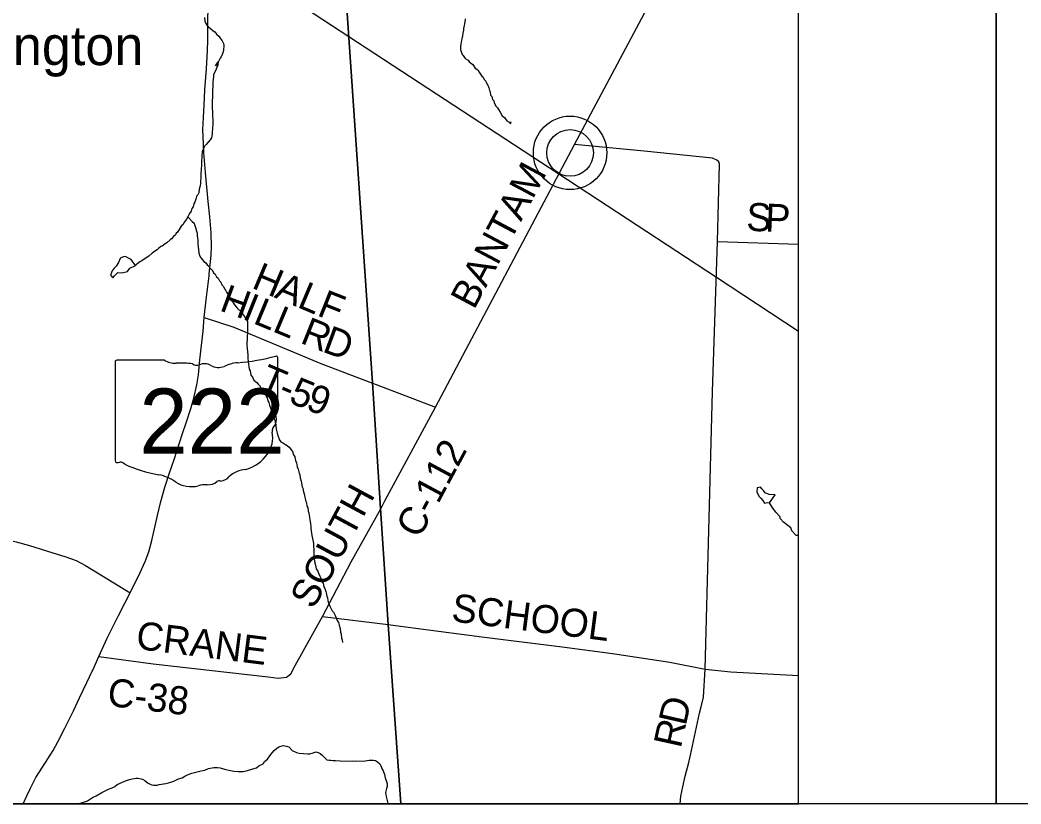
# Model space of a CAD drawing. Extents: x 0 to 39.3, y -3.9 to 22.
# Drawn here: x 7.123 to 9.15, y 13.9 to 15.488 of the extents above; entities that cross this region are included whole.
import ezdxf

# ---------------------------------------------------------------- set-up
doc = ezdxf.new("R2010")
doc.units = 0
for name, color, linetype in [('GM_X_Corporation', 7, 'Continuous'), ('GM_X_County_Road', 7, 'Continuous'), ('GM_X_County_Road_Text', 7, 'Continuous'), ('GM_X_Minor_Lake', 7, 'Continuous'), ('GM_X_Minor_River', 7, 'Continuous'), ('GM_X_Rail_Line', 7, 'Continuous'), ('GM_X_State_Location', 7, 'Continuous'), ('GM_X_State_Route', 7, 'Continuous'), ('GM_X_State_Shield', 7, 'Continuous'), ('GM_X_Township_Road', 7, 'Continuous'), ('GM_X_Township_Road_Text', 7, 'Continuous'), ('GM_X_Unincorporated', 7, 'Continuous'), ('GM_X_Unincorporated_Location', 7, 'Continuous'), ('GM_X_Unincorporated_Text', 7, 'Continuous'), ('SH_Data', 7, 'Continuous'), ('SH_Text', 7, 'Continuous')]:
    doc.layers.add(name, color=color, linetype=linetype)

msp = doc.modelspace()

# ---------------------------------------------------------------- linework, layer by layer
at = {"layer": 'GM_X_Corporation'}
msp.add_lwpolyline([(7.894, 13.9), (8.7, 13.9), (8.7, 17.1372), (7.6633, 17.2343), (7.7024, 16.7078), (7.7245, 16.3862), (7.7384, 16.1852), (7.7467, 16.0631), (7.8368, 14.7531), (7.8533, 14.4986), (7.8685, 14.2638)], close=True, dxfattribs=at)
msp.add_lwpolyline([(3.8692, 13.9), (7.894, 13.9), (7.8685, 14.2638), (7.8533, 14.4986), (7.8368, 14.7531), (7.7467, 16.0631)], dxfattribs=at)
at = {"layer": 'GM_X_County_Road'}
for points in [[(7.8619, 14.5137), (7.9642, 14.7038), (8.2458, 15.2359), (8.4264, 15.5749), (8.4473, 15.6168), (8.4536, 15.6361), (8.4563, 15.6574), (8.4613, 15.7093), (8.4729, 15.8197), (8.4859, 15.9546)], [(6.0819, 14.5477), (6.1075, 14.544), (6.1751, 14.5372), (6.2211, 14.532), (6.2642, 14.5267), (6.488, 14.5027), (6.5996, 14.4912), (6.8005, 14.4678), (7.0043, 14.4459), (7.0661, 14.4409), (7.0915, 14.4369), (7.1149, 14.4309), (7.1423, 14.4234), (7.1872, 14.4095), (7.2156, 14.4005), (7.2365, 14.393), (7.2555, 14.3831), (7.2799, 14.3681), (7.3458, 14.3278)], [(7.7356, 14.2798), (7.7938, 14.3902), (7.8535, 14.4981), (7.8619, 14.5137)], [(7.2825, 14.1984), (7.3922, 14.184), (7.6254, 14.1576), (7.6458, 14.155), (7.6627, 14.1568), (7.6715, 14.1634), (7.6802, 14.1808), (7.7356, 14.2798), (7.8688, 14.2633), (7.8933, 14.2601)], [(7.8933, 14.2601), (8.0581, 14.2387), (8.2213, 14.2186), (8.3233, 14.2046), (8.439, 14.1869), (8.5108, 14.1731)], [(8.5108, 14.1731), (8.5626, 14.1676), (8.7, 14.1603)]]:
    msp.add_lwpolyline(points, dxfattribs=at)
at = {"layer": 'GM_X_Minor_Lake'}
for points in [[(7.3322, 15.0079), (7.3268, 15.0064), (7.3257, 15.0049), (7.3221, 14.997), (7.3174, 14.9895), (7.3136, 14.985), (7.3093, 14.9798), (7.3061, 14.9707), (7.3109, 14.9653), (7.3141, 14.9698), (7.321, 14.9761), (7.329, 14.976), (7.3404, 14.9785), (7.3451, 14.9852), (7.3567, 14.9908)], [(7.3567, 14.9908), (7.3478, 15.0026), (7.3413, 15.0062), (7.3367, 15.0089), (7.3322, 15.0079)], [(8.6413, 14.5102), (8.6525, 14.5258), (8.6404, 14.5271), (8.6325, 14.5299), (8.6287, 14.5346), (8.6258, 14.5384), (8.6228, 14.5415), (8.6163, 14.5405), (8.615, 14.5321), (8.6191, 14.5237), (8.6232, 14.5191), (8.6273, 14.5144)], [(8.6273, 14.5144), (8.6306, 14.5091), (8.636, 14.5106), (8.6413, 14.5102)]]:
    msp.add_lwpolyline(points, dxfattribs=at)
at = {"layer": 'GM_X_Minor_River'}
for points in [[(7.4968, 15.4926), (7.4974, 15.4853), (7.4993, 15.4807), (7.5015, 15.4773), (7.5048, 15.4738), (7.5142, 15.4656), (7.5172, 15.4637), (7.5206, 15.459), (7.5254, 15.4548), (7.528, 15.4509), (7.5325, 15.4455), (7.5351, 15.4401), (7.5354, 15.4367), (7.5352, 15.4261), (7.5336, 15.4211), (7.53, 15.4132), (7.5281, 15.4102), (7.5257, 15.4053), (7.5225, 15.4), (7.5186, 15.3947), (7.5241, 15.403)], [(8.0248, 15.4903), (8.0244, 15.4872), (8.0231, 15.4804), (8.0223, 15.4766), (8.0214, 15.4705), (8.021, 15.4671), (8.0197, 15.461), (8.0189, 15.4557), (8.0176, 15.4496), (8.0168, 15.447), (8.0159, 15.439), (8.0151, 15.4341), (8.0149, 15.4272), (8.0164, 15.4238), (8.0182, 15.418), (8.0208, 15.4157), (8.0245, 15.4096), (8.0305, 15.4064), (8.0324, 15.4033), (8.0403, 15.3979), (8.0451, 15.3902), (8.05, 15.387), (8.0526, 15.3821), (8.0585, 15.3743), (8.0611, 15.372), (8.063, 15.3674), (8.0663, 15.3639), (8.0685, 15.3582), (8.0707, 15.3555), (8.0722, 15.3505), (8.074, 15.3448), (8.0751, 15.3421), (8.0761, 15.3356), (8.0783, 15.3329), (8.0801, 15.3268), (8.0823, 15.3241), (8.0834, 15.321), (8.0867, 15.3133), (8.0901, 15.3102), (8.0923, 15.3064), (8.0953, 15.3014), (8.0993, 15.2937), (8.1042, 15.2902), (8.1086, 15.2836), (8.1135, 15.2809), (8.1165, 15.2778), (8.1178, 15.2823)], [(7.5241, 15.403), (7.5232, 15.3962), (7.5181, 15.3833), (7.5145, 15.3773), (7.5145, 15.3743), (7.5139, 15.3663), (7.5135, 15.3632), (7.513, 15.3355), (7.5125, 15.3313), (7.512, 15.3244), (7.5119, 15.3145), (7.5121, 15.3077), (7.5124, 15.3035), (7.5127, 15.2955), (7.513, 15.2928), (7.5133, 15.2864), (7.5131, 15.2749), (7.5126, 15.2711), (7.5125, 15.267), (7.512, 15.2613), (7.512, 15.2582), (7.5115, 15.2529), (7.5107, 15.2491), (7.5079, 15.245), (7.5041, 15.2405), (7.5002, 15.2356), (7.4975, 15.2333), (7.4943, 15.2277), (7.4915, 15.2205), (7.491, 15.2129), (7.4907, 15.1992), (7.4902, 15.1912), (7.4898, 15.1886), (7.4897, 15.1828), (7.4892, 15.1783), (7.4891, 15.1692), (7.4885, 15.16), (7.4885, 15.1574), (7.488, 15.152), (7.486, 15.1452), (7.4851, 15.138), (7.4831, 15.1339), (7.4804, 15.1309), (7.4795, 15.1267), (7.4767, 15.1191), (7.4751, 15.1157), (7.4735, 15.1093), (7.4708, 15.1059), (7.4692, 15.1006), (7.4664, 15.0957), (7.4625, 15.0889), (7.4593, 15.0833), (7.4551, 15.0784), (7.4531, 15.0735), (7.4492, 15.0701), (7.4472, 15.0667), (7.4421, 15.0581), (7.4394, 15.0558), (7.4375, 15.0528), (7.4336, 15.0494), (7.4297, 15.0446), (7.427, 15.0423), (7.42, 15.0364), (7.4166, 15.0345), (7.4108, 15.03), (7.4081, 15.0289), (7.4035, 15.0248), (7.4004, 15.0222), (7.393, 15.0174), (7.3904, 15.0159), (7.3834, 15.0092), (7.3784, 15.0062), (7.3695, 15.0003), (7.3657, 14.9981), (7.3595, 14.9936), (7.3567, 14.9908)], [(7.4625, 15.0889), (7.4716, 15.0797), (7.4753, 15.0766), (7.476, 15.0739), (7.4789, 15.0655), (7.4796, 15.0621), (7.4814, 15.056), (7.4817, 15.0506), (7.482, 15.0472), (7.4827, 15.0419), (7.4833, 15.035), (7.484, 15.0274), (7.4843, 15.0228), (7.4853, 15.0156), (7.4867, 15.0117), (7.4878, 15.0083), (7.49, 15.0056), (7.4949, 14.999), (7.4986, 14.9967), (7.5016, 14.9921), (7.505, 14.9893), (7.5079, 14.9843), (7.5117, 14.9816), (7.5146, 14.9758), (7.5184, 14.9731), (7.5209, 14.9677), (7.5243, 14.965), (7.5269, 14.9596), (7.5295, 14.9569), (7.5317, 14.9512), (7.5347, 14.9481), (7.5369, 14.9435), (7.5391, 14.9408), (7.5409, 14.9366), (7.5447, 14.9319), (7.545, 14.9289), (7.5487, 14.9227), (7.5509, 14.9196), (7.555, 14.9142), (7.5572, 14.9112), (7.5613, 14.9065), (7.5636, 14.9038), (7.5699, 14.8972), (7.5733, 14.893), (7.5755, 14.8899), (7.5818, 14.8807), (7.5836, 14.8772), (7.5838, 14.8677), (7.5834, 14.8624), (7.5836, 14.8532), (7.5831, 14.8487), (7.5826, 14.8395), (7.5821, 14.8357), (7.5824, 14.8281), (7.5831, 14.8239), (7.5833, 14.8148), (7.584, 14.8106), (7.5845, 14.8014), (7.5852, 14.7972), (7.5859, 14.7896), (7.5866, 14.7866), (7.5868, 14.7809), (7.5887, 14.7774), (7.5904, 14.7686), (7.5938, 14.7644), (7.5963, 14.7582), (7.6023, 14.7536), (7.6053, 14.7501), (7.6079, 14.7474), (7.6105, 14.7431), (7.6143, 14.7408), (7.6161, 14.7366), (7.6187, 14.7335), (7.6205, 14.727), (7.6231, 14.7228), (7.6249, 14.7166), (7.6267, 14.7132), (7.6281, 14.7074), (7.6307, 14.7005), (7.6321, 14.6971), (7.6335, 14.6895), (7.6361, 14.6856), (7.6375, 14.6799), (7.639, 14.6772), (7.6397, 14.6734), (7.6408, 14.6684), (7.6411, 14.6638), (7.6421, 14.6562), (7.6439, 14.6508), (7.646, 14.6443), (7.6468, 14.6417), (7.6478, 14.6382), (7.6508, 14.6332), (7.6549, 14.6312)], [(7.6549, 14.6312), (7.664, 14.6261), (7.6681, 14.6226), (7.6726, 14.6165), (7.6748, 14.6138), (7.6766, 14.6069), (7.6796, 14.603), (7.6809, 14.5954), (7.6828, 14.5912), (7.6845, 14.5828), (7.6863, 14.5778), (7.6881, 14.5698), (7.6899, 14.5663), (7.6906, 14.5606), (7.692, 14.5537), (7.6931, 14.5499), (7.6944, 14.5426), (7.6959, 14.5396), (7.6969, 14.5323), (7.6984, 14.5281), (7.6994, 14.5216), (7.7005, 14.5189), (7.7015, 14.5128), (7.703, 14.5097), (7.704, 14.5033), (7.7055, 14.5002), (7.7065, 14.4929), (7.7076, 14.4899), (7.7082, 14.4842), (7.7089, 14.4811), (7.7096, 14.4758), (7.7103, 14.4719), (7.7114, 14.4677), (7.7116, 14.462), (7.712, 14.4582), (7.714, 14.4437), (7.7154, 14.4376), (7.7164, 14.4307), (7.7171, 14.4273), (7.7174, 14.4201), (7.7181, 14.4166), (7.718, 14.4113), (7.7182, 14.4044), (7.7184, 14.3961), (7.7195, 14.3926), (7.7202, 14.3877), (7.7216, 14.3838), (7.723, 14.3762), (7.7264, 14.3716), (7.7274, 14.3674), (7.73, 14.3612), (7.7318, 14.3585), (7.7336, 14.3513), (7.7366, 14.347), (7.738, 14.3401), (7.7402, 14.3363), (7.742, 14.3302), (7.7431, 14.3275), (7.7441, 14.3206), (7.7456, 14.3172), (7.7466, 14.3122), (7.7477, 14.3076), (7.7502, 14.3004), (7.7517, 14.2977), (7.7554, 14.2915), (7.7576, 14.2888), (7.7613, 14.2819), (7.7653, 14.2719), (7.7679, 14.2673), (7.7693, 14.262), (7.7711, 14.2555), (7.7721, 14.2478), (7.7735, 14.2436), (7.7742, 14.236), (7.7752, 14.2322), (7.7763, 14.2272)], [(8.7, 14.4437), (8.6949, 14.4438), (8.6859, 14.4531), (8.6845, 14.4592), (8.6691, 14.4709), (8.6635, 14.4774), (8.6621, 14.482), (8.6535, 14.4913), (8.6465, 14.5013), (8.6413, 14.5102)], [(7.2311, 13.9), (7.2336, 13.9003), (7.2401, 13.9013), (7.2447, 13.9016), (7.2496, 13.9031), (7.2596, 13.9067), (7.2696, 13.913), (7.2773, 13.9163), (7.2888, 13.9233), (7.2977, 13.9277), (7.3023, 13.9299), (7.3092, 13.9329), (7.3149, 13.9354), (7.3196, 13.9395), (7.3303, 13.9439), (7.3368, 13.9468), (7.3445, 13.9497), (7.3502, 13.9508), (7.3579, 13.9522), (7.3621, 13.9521), (7.3712, 13.9504), (7.3753, 13.9473), (7.3809, 13.943), (7.3862, 13.9399), (7.39, 13.9387), (7.3938, 13.9379), (7.4006, 13.9381), (7.4048, 13.9392), (7.4182, 13.9412), (7.4236, 13.9431), (7.4285, 13.9445), (7.4343, 13.9463), (7.4439, 13.9507), (7.4515, 13.9532), (7.4569, 13.9562), (7.4623, 13.9588), (7.4711, 13.9624), (7.4872, 13.9667), (7.4933, 13.9681), (7.4971, 13.9688), (7.5044, 13.9717), (7.5155, 13.9738), (7.5231, 13.9737), (7.528, 13.9732), (7.5326, 13.972), (7.5398, 13.9696), (7.5458, 13.9683), (7.5561, 13.9663), (7.5648, 13.9657), (7.5751, 13.9659), (7.5835, 13.9677), (7.5942, 13.9709), (7.6019, 13.9731), (7.6065, 13.9772), (7.615, 13.9816), (7.6181, 13.9861), (7.6239, 13.991), (7.629, 13.9974), (7.6333, 14.0034), (7.6379, 14.0086), (7.6433, 14.0131), (7.6472, 14.0157), (7.6556, 14.0182), (7.6628, 14.0173), (7.667, 14.0157), (7.6744, 14.008), (7.6831, 14.0044), (7.6881, 14.0032), (7.6972, 14.0023), (7.7059, 14.0017), (7.7097, 14.0017), (7.7147, 14.0031), (7.7185, 14.0042), (7.7227, 14.0053), (7.7269, 14.0044), (7.7311, 14.0025), (7.7348, 13.9986), (7.7393, 13.9939), (7.7445, 13.9897), (7.7487, 13.9888), (7.7525, 13.9884), (7.7567, 13.9883), (7.7616, 13.9878), (7.7715, 13.9873), (7.7963, 13.9869), (7.8016, 13.9872), (7.8183, 13.9869), (7.8222, 13.9872), (7.8298, 13.9886)], [(7.8298, 13.9886), (7.8336, 13.9889), (7.8389, 13.9888), (7.8431, 13.9883), (7.8472, 13.9852), (7.8517, 13.9813), (7.8536, 13.9771), (7.8565, 13.9706), (7.8583, 13.9668), (7.8609, 13.9599), (7.8626, 13.953), (7.8652, 13.9457), (7.8666, 13.9407), (7.8665, 13.9354), (7.8653, 13.9313), (7.8632, 13.9233), (7.8642, 13.9153), (7.8657, 13.9096), (7.8682, 13.9015), (7.8689, 13.9)], [(8.7, 13.9031), (8.6992, 13.9025), (8.6971, 13.9)]]:
    msp.add_lwpolyline(points, dxfattribs=at)
at = {"layer": 'GM_X_Rail_Line'}
msp.add_lwpolyline([(5.9697, 16.6744), (6.1991, 16.4081), (6.2218, 16.3901), (6.3667, 16.3031), (6.4893, 16.2389), (7.0583, 15.9241), (7.1182, 15.89), (7.5253, 15.6271), (8.2122, 15.1777), (8.5334, 14.9668), (8.7, 14.8573)], dxfattribs=at)
at = {"layer": 'GM_X_State_Route'}
for points in [[(7.5062, 14.9738), (7.5079, 14.9918), (7.5101, 15.0116), (7.5109, 15.0289), (7.5099, 15.057), (7.5076, 15.0895), (7.5041, 15.1204), (7.4986, 15.1789), (7.4952, 15.2192), (7.4944, 15.2368), (7.4931, 15.2662), (7.4943, 15.2903), (7.4956, 15.3156), (7.4974, 15.3466), (7.5005, 15.3886), (7.5027, 15.4261), (7.503, 15.4463), (7.5032, 15.4895), (7.5041, 15.5091), (7.506, 15.5264), (7.511, 15.5543), (7.5122, 15.5592)], [(7.27, 14.1711), (7.2825, 14.1984), (7.2992, 14.2357), (7.3224, 14.282), (7.3353, 14.3065), (7.3458, 14.3278), (7.3661, 14.3691), (7.3763, 14.391), (7.3834, 14.4105), (7.3898, 14.4337), (7.4015, 14.4845), (7.4078, 14.5126), (7.416, 14.5415), (7.4256, 14.5704), (7.4348, 14.598), (7.4521, 14.6505), (7.4596, 14.6718), (7.4694, 14.7033), (7.4752, 14.7221), (7.481, 14.7491), (7.4844, 14.7693), (7.4871, 14.7995), (7.4938, 14.8578), (7.496, 14.885), (7.5002, 14.9211), (7.5046, 14.9588), (7.5058, 14.9698), (7.5062, 14.9738)], [(7.1294, 13.9), (7.1369, 13.9165), (7.1439, 13.9323), (7.155, 13.9538), (7.1681, 13.9745), (7.1793, 13.9917), (7.1898, 14.0085), (7.1996, 14.0256), (7.2135, 14.0533), (7.2313, 14.0888), (7.2431, 14.1151), (7.258, 14.1462), (7.2692, 14.1693), (7.27, 14.1711)]]:
    msp.add_lwpolyline(points, dxfattribs=at)
at = {"layer": 'GM_X_State_Shield'}
for p, q in [((7.6451, 14.6992), (7.6451, 14.8039)), ((7.3155, 14.7955), (7.3155, 14.5954)), ((7.4153, 14.7989), (7.3187, 14.7989)), ((7.645, 14.6992), (7.6451, 14.6992))]:
    msp.add_line(p, q, dxfattribs=at)
for centre, major_axis, start_param, end_param in [((7.5277, 15.0718), (0.3495, 0), 4.814394, 5.042369), ((7.6414, 14.8043), (0.00367, 0), 6.141152, 7.989035), ((7.3193, 14.7959), (0.00382, 0), 1.712693, 3.28349), ((7.4382, 14.8222), (0.037, 0), 4.042523, 4.731795), ((7.4505, 14.6866), (0.133, 0), 1.404758, 1.657858), ((7.4807, 14.797), (0.0107, 0), 3.836095, 5.185415), ((7.4964, 14.7738), (0.0222, 0), 0.950623, 2.079405), ((7.5251, 14.8055), (0.0267, 0), 4.081561, 5.145723), ((7.5723, 14.7378), (0.0703, 0), 1.699011, 2.107814), ((7.6442, 14.6915), (0.00568, 0), 1.883978, 3.671073), ((7.6081, 14.6783), (0.0341, 0), 5.934695, 6.695948), ((7.6412, 14.6988), (0.00393, 0), 5.05454, 6.418171), ((7.6582, 14.6554), (0.0248, 0), 2.387724, 3.262537), ((7.5473, 14.6421), (0.0874, 0), 5.101752, 6.440018), ((7.3193, 14.5949), (0.00385, 0), 3.00124, 4.508301), ((7.3199, 14.6154), (0.0294, 0), 4.665946, 4.897461), ((7.3259, 14.5838), (0.0106, 0), 0.519207, 1.627899), ((7.4597, 14.7636), (0.2524, 0), 4.195997, 4.488961), ((7.3845, 14.5055), (0.079, 0), 0.823519, 1.323587), ((7.5235, 14.576), (0.0282, 0), 4.937069, 5.64225), ((7.5841, 14.5392), (0.0479, 0), 1.647645, 2.488434), ((7.4699, 14.5828), (0.0501, 0), 4.026481, 4.996735), ((7.4988, 14.5136), (0.0412, 0), 1.495662, 1.94098), ((7.5025, 14.5678), (0.0267, 0), 4.691044, 5.507374), ((7.5267, 14.5485), (0.00752, 0), 1.147584, 2.315152)]:
    msp.add_ellipse(centre, major_axis=major_axis, ratio=0.8, start_param=start_param, end_param=end_param, dxfattribs=at)
at = {"layer": 'GM_X_Township_Road'}
for p, q in [((8.5359, 15.0392), (8.7, 15.0337)), ((7.8444, 14.7497), (7.9642, 14.7038))]:
    msp.add_line(p, q, dxfattribs=at)
for points in [[(8.4603, 13.9), (8.4616, 13.9156), (8.4653, 13.9349), (8.4701, 13.9565), (8.4777, 13.9842), (8.4812, 13.9987), (8.4995, 14.0836), (8.5028, 14.097), (8.5076, 14.1161), (8.5108, 14.1731), (8.5253, 14.7348), (8.5359, 15.0392), (8.5398, 15.1959), (8.5381, 15.2006), (8.5342, 15.2042), (8.5256, 15.2078), (8.3871, 15.2223), (8.2458, 15.2359)], [(7.496, 14.885), (7.556, 14.8659), (7.732, 14.7922), (7.837, 14.7526), (7.8444, 14.7497)]]:
    msp.add_lwpolyline(points, dxfattribs=at)
at = {"layer": 'GM_X_Unincorporated'}
for radius in [0.0744, 0.0472]:
    msp.add_circle((8.237, 15.2187), radius, dxfattribs=at)
at = {"layer": 'GM_X_Unincorporated_Location'}
msp.add_line((8.237, 15.2187), (8.237, 15.2187), dxfattribs=at)
at = {"layer": 'SH_Data'}
msp.add_lwpolyline([(1.9, 21.1), (9.1, 21.1), (9.1, 13.9), (1.9, 13.9)], close=True, dxfattribs=at)
at = {"layer": 'SH_Text'}
msp.add_lwpolyline([(9.1, 21.1), (11.7047, 21.1), (11.7047, 13.9), (9.1, 13.9)], close=True, dxfattribs=at)

# ---------------------------------------------------------------- texts
at = {"layer": 'GM_X_County_Road_Text'}
for s, rotation, p in [('BANTAM', 62.012, (8.0425, 14.8994)), ('C-112', 61.7166, (7.9316, 14.4353)), ('SOUTH', 61.6855, (7.7173, 14.2924)), ('SCHOOL', 352.7468, (7.995, 14.2703)), ('CRANE', 352.8747, (7.3558, 14.2144)), ('C-38', 353.0887, (7.2978, 14.0992))]:
    msp.add_text(s, height=0.05682, rotation=rotation, dxfattribs=at).set_placement(p)
at = {"layer": 'GM_X_State_Location'}
for s in ['s', 'r']:
    msp.add_text(s, height=0.000189, dxfattribs=at).set_placement((7.4766, 14.6821))
msp.add_text('222', height=0.000189, rotation=0, dxfattribs=at).set_placement((7.4097, 14.6683))
at = {"layer": 'GM_X_State_Shield'}
msp.add_text('222', height=0.13184, dxfattribs=at).set_placement((7.3645, 14.6095))
at = {"layer": 'GM_X_Township_Road_Text'}
for s, rotation, p in [('S', 357.4048, (8.5931, 15.0613)), ('P', 357.4048, (8.6314, 15.0595)), ('H', 337.0996, (7.5899, 14.946)), ('A', 337.0998, (7.636, 14.9265)), ('H', 339.7833, (7.5248, 14.9002)), ('L', 337.0999, (7.6821, 14.9071)), ('I', 338.0652, (7.5713, 14.8831)), ('L', 337.394, (7.5928, 14.8744)), ('F', 338.241, (7.7224, 14.8901)), ('L', 337.2826, (7.632, 14.8581)), ('R', 338.1859, (7.6882, 14.8346)), ('D', 339.7217, (7.7331, 14.8167)), ('T', 336.9483, (7.6036, 14.7398)), ('5', 337.7487, (7.665, 14.7138)), ('-', 337.1276, (7.6429, 14.7231)), ('9', 339.5557, (7.6992, 14.6998)), ('D', 77.1614, (8.4712, 14.0567)), ('R', 77.5855, (8.4612, 14.0112))]:
    msp.add_text(s, height=0.0568, rotation=rotation, dxfattribs=at).set_placement(p)
at = {"layer": 'GM_X_Unincorporated_Text'}
msp.add_text('Hulington', height=0.07898, rotation=0, dxfattribs=at).set_placement((6.9264, 15.3964))

doc.saveas('drawing.dxf')
